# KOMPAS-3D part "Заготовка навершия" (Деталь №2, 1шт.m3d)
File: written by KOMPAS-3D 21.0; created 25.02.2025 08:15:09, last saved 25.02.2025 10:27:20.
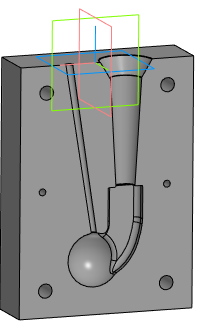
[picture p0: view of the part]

Document properties: Автор: User; Полное имя файла: C:\Users\Цыба.НГ\Работа\Прочее\Колян\Гарда\Форма для литья навершия.m3d

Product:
- Part/product: Заготовка навершия
    Масса: 3.099981

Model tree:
1. Эскиз:1
2. Элемент выдавливания:1
     Расстояние 2 = 140
3. Вычесть компоненты:1
4. Скругление:1  (with: Вычесть компоненты:1)
     Радиус = 0.5
5. Эскиз:2  (with: Элемент выдавливания:1)
6. Элемент выдавливания:2
     Расстояние 2 = 100
7. Эскиз:3  (with: Элемент выдавливания:2)
8. Элемент выдавливания:3
9. Эскиз:4  (with: Элемент выдавливания:2)
10. Элемент выдавливания:4
     Расстояние 2 = 10

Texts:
  Точка начала. Х
  Точка начала. Y
  Точка начала. Z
